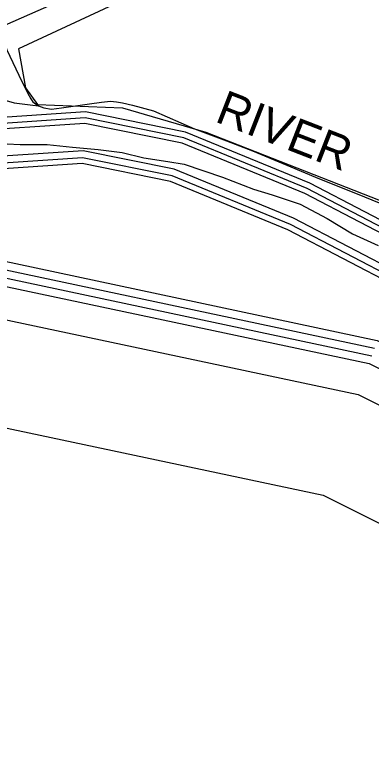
# Model space of a CAD drawing. Extents: x 2260773 to 2342389, y 552869 to 618546.
# Drawn here: x 2273724 to 2275474, y 592207 to 595865 of the extents above; entities that cross this region are included whole.
import ezdxf

# ---------------------------------------------------------------- set-up
doc = ezdxf.new("R2010")
doc.units = 0
for name, color, linetype in [('Exist Hydrographic Buffer Line', 7, 'Continuous'), ('Exist Hydrographic Lake Shore', 7, 'Continuous'), ('Exist Hydrographic Misc Water Feature', 7, 'Continuous'), ('Exist Hydrographic Pond Under 1500 Sq Ft', 7, 'Continuous'), ('Exist Hydrographic River Shore', 7, 'Continuous'), ('Exist Hydrographic River Shore Label', 7, 'Continuous'), ('Exist Road Non-System Type 51', 7, 'Continuous')]:
    doc.layers.add(name, color=color, linetype=linetype)

msp = doc.modelspace()

# ---------------------------------------------------------------- linework, layer by layer
at = {"layer": 'Exist Hydrographic Buffer Line'}
for points in [[(2280865.9, 594984.5), (2280052.8, 595165.8), (2279251.2, 595104.9), (2278777.9, 594983.9), (2278410.6, 594835.1), (2277854.3, 594325.9), (2277304, 594136.6), (2276736.5, 594234), (2276241.4, 594447.3), (2275159.9, 595011.2), (2274553.8, 595261.2), (2274069.4, 595358.9), (2273472.5, 595318.3), (2271849.6, 595062.1), (2271324.1, 595102.3)], [(2280857.6, 594958.9), (2280050.9, 595138.8), (2279255.6, 595078.4), (2278786.3, 594958.4), (2278425.1, 594812.1), (2277868.3, 594302.4), (2277306.3, 594109), (2276728.8, 594208.1), (2276229.9, 594423.1), (2275148.5, 594986.9), (2274545.9, 595235.4), (2274067.6, 595331.9), (2273475.5, 595291.6), (2271850.6, 595035.1), (2271322, 595075.6)], [(2280816.3, 594831.7), (2280041.2, 595004.5), (2279277.3, 594946.4), (2278828, 594831.5), (2278497.3, 594697.6), (2277937.8, 594185.5), (2277317.3, 593971.9), (2276690.7, 594079.5), (2276172.7, 594302.7), (2275092.3, 594866), (2274507, 595107.4), (2274058.8, 595197.8), (2273490.5, 595159.1), (2271856, 594901.1), (2271212.2, 594950.4)], [(2280805.8, 594799.1), (2280038.8, 594970.1), (2279282.9, 594912.6), (2278838.7, 594799.1), (2278515.8, 594668.3), (2277955.6, 594155.5), (2277320.2, 593936.8), (2276680.9, 594046.6), (2276158, 594271.9), (2275077.8, 594835), (2274497, 595074.6), (2274056.6, 595163.4), (2273494.3, 595125.2), (2271857.4, 594866.8), (2271248.4, 594913.4)], [(2275682.8, 590886.2), (2275298.9, 590908.5), (2274110.7, 590732.1), (2273660.6, 590686.4), (2273419.8, 590746.1), (2273239.6, 590939.8), (2273099.1, 591260.2), (2273064.9, 591446.4), (2272764.3, 591973.6), (2272546.3, 592252.6), (2272507.6, 592371.6), (2272512.7, 592725.7), (2272500.6, 592922.5), (2272230.5, 593239), (2272233.4, 593780.7), (2272721, 593822.7), (2272786.6, 593913.3), (2272785.8, 594399.9), (2273028.6, 594725.2), (2273146.3, 594725.5), (2275490.4, 594227.2)], [(2275694.1, 590924.5), (2275301.2, 590948.4), (2274105.5, 590771.8), (2273663.4, 590726.9), (2273441, 590782.1), (2273273.4, 590962), (2273137.7, 591271.9), (2273104.3, 591453.7), (2272798.9, 591993.5), (2272582.4, 592271.8), (2272547.7, 592377.7), (2272552.7, 592725.1), (2272540.4, 592925), (2272521.9, 592971.5), (2272270.9, 593254.1), (2272273.4, 593744), (2272724.3, 593782.9), (2272769, 593801.3), (2272822.5, 593895.9), (2272825.8, 594386.8), (2273048.9, 594685.3), (2273142.4, 594685.5), (2275477.1, 594189.2)], [(2272833.6, 592013.5), (2272618.1, 592290.8), (2272587.9, 592383.8), (2272592.6, 592724.6), (2272580.3, 592927.4), (2272564.6, 592980), (2272310.9, 593269.2), (2272313.2, 593707.3), (2272727.8, 593743), (2272777.6, 593758.7), (2272809.6, 593785.5), (2272858.6, 593878.5), (2272870.5, 593930.8), (2272866, 594373.7), (2273068.8, 594645.4), (2273138.1, 594645.5), (2275463.8, 594151.1), (2276254.1, 593757.8)], [(2272972.4, 592093.3), (2272761.6, 592367.2), (2272748.1, 592408.1), (2272752.6, 592722.4), (2272740.1, 592937.3), (2272723.7, 593015.8), (2272703.2, 593060), (2272675.1, 593100), (2272471.1, 593329.7), (2272472.3, 593560.4), (2272741.5, 593583.6), (2272813.3, 593599.5), (2272857.6, 593620.1), (2272897.6, 593648.1), (2272932, 593682.6), (2272960.1, 593722.6), (2273002.5, 593808.8), (2273026.3, 593882.1), (2273030.6, 593930.8), (2273026.5, 594321.3), (2273148.1, 594479.8), (2275410.7, 593998.8), (2276182.9, 593614.6)], [(2273719.2, 591838.2), (2273423.1, 592352.6), (2273359.5, 592446.6), (2273270.3, 592560.7), (2273272.6, 592715.2), (2273271.2, 592775.7), (2273259.1, 592969.5), (2273248.4, 593059), (2273212.3, 593193.6), (2273231.8, 593249.8), (2273330.4, 593348.3), (2273410.4, 593462.6), (2273437.7, 593514.1), (2273470.7, 593582.3), (2273502.3, 593657.2), (2273538.3, 593791.8), (2273544.9, 593863.8), (2275238, 593503.8), (2275951.4, 593149)]]:
    msp.add_lwpolyline(points, dxfattribs=at)
at = {"layer": 'Exist Hydrographic Lake Shore'}
msp.add_lwpolyline([(2272472.5, 592726.3), (2272460.6, 592920), (2272190.5, 593223.9), (2272193.6, 593817.5), (2272717.5, 593862.6), (2272750.5, 593930.8), (2272745.6, 594413), (2273008.5, 594765.2), (2273150.6, 594765.5), (2275503.6, 594265.3), (2276307.6, 593865.3), (2276724.7, 593742), (2277233.6, 593689.1), (2277591.6, 593708.1), (2277964.6, 593880.9), (2279148.6, 594591.5), (2279472.8, 594693.2), (2279788.7, 594722.9), (2280180.6, 594659.1), (2280557.7, 594530.2)], dxfattribs=at)
at = {"layer": 'Exist Hydrographic Misc Water Feature'}
msp.add_lwpolyline([(2273686.6, 595230.8), (2273750.8, 595227.6), (2273882.6, 595228.8), (2274006.7, 595215.8), (2274132.6, 595203.3), (2274251.3, 595188.3), (2274357.1, 595163.4), (2274475.6, 595144.3), (2274555.4, 595131.1), (2274743.6, 595067), (2274896.2, 595008.3), (2274988.7, 594981.4), (2275125, 594934.5), (2275257.7, 594863.8), (2275382.2, 594789.1), (2275508.7, 594732.3)], dxfattribs=at)
at = {"layer": 'Exist Hydrographic Pond Under 1500 Sq Ft'}
msp.add_lwpolyline([(2277070.6, 594204), (2277552.7, 594351.7), (2277593.7, 594377.1), (2277566.6, 594590.8), (2276469.6, 596931.7), (2276345.7, 596911.2), (2273741.6, 595698.1), (2273776.6, 595507.2), (2273835.7, 595424), (2274252.5, 595409), (2274661.6, 595289.2), (2275798.6, 594843.1), (2276636.7, 594301.3), (2276936.7, 594210), (2277070.6, 594204)], dxfattribs=at)
at = {"layer": 'Exist Hydrographic River Shore'}
for points in [[(2280875, 595012.6), (2280055, 595195.4), (2279246.4, 595134), (2278768.7, 595011.9), (2278394.6, 594860.4), (2277839, 594351.7), (2277301.6, 594166.8), (2276744.9, 594262.4), (2276254.1, 594473.9), (2275172.3, 595037.8), (2274562.3, 595289.4), (2274071.4, 595388.5), (2273469.2, 595347.5), (2271848.4, 595091.7), (2271326.3, 595131.6)], [(2280796.8, 594771.4), (2280036.7, 594940.8), (2279287.6, 594883.9), (2278847.8, 594771.5), (2278531.6, 594643.4), (2277970.8, 594130.1), (2277322.6, 593907), (2276672.6, 594018.6), (2276145.6, 594245.7), (2275065.6, 594808.7), (2274488.6, 595046.7), (2274054.7, 595134.2), (2273497.5, 595096.4), (2271858.6, 594837.6), (2271275.6, 594882.2)]]:
    msp.add_lwpolyline(points, dxfattribs=at)
at = {"layer": 'Exist Road Non-System Type 51'}
for points in [[(2277564.5, 594796.9), (2277510.4, 594924.8), (2277417.1, 595141.1), (2277242.6, 595529.5), (2277065.7, 595905.7), (2276903.5, 596267.1), (2276758.6, 596601.4), (2276621, 596891.5), (2276579.2, 596975.1), (2276544.8, 597016.9), (2276525.1, 597029.2), (2276488.3, 597043.9), (2276449, 597048.9), (2276419.5, 597046.4), (2276370.3, 597034.1), (2276247.5, 596984.9), (2275893.7, 596825.1), (2275414.5, 596603.9), (2274687.2, 596279.4), (2274237.6, 596070.4), (2273904.6, 595915.5), (2273645.4, 595802.4)], [(2273645.4, 595802.4), (2273684.7, 595694.3), (2273743.7, 595568.9), (2273785.5, 595482.8), (2273802.7, 595453.3), (2273812.5, 595438.6), (2273824.8, 595428.7), (2273839.5, 595418.9)], [(2273174.9, 595623), (2273238.8, 595591), (2273366.5, 595544.3), (2273518.9, 595497.6), (2273634.4, 595458.2), (2273720.4, 595433.7), (2273812.5, 595421.4), (2273839.5, 595418.9)], [(2273839.5, 595418.9), (2273866.6, 595409.1), (2273903.4, 595401.7), (2273952.6, 595409.1), (2274021.4, 595418.9), (2274090.1, 595428.7), (2274149.1, 595436.1), (2274193.3, 595441), (2274222.8, 595438.6), (2274252.3, 595433.7), (2274301.5, 595421.4), (2274404.7, 595394.3), (2274606.1, 595305.8), (2274763.4, 595246.8), (2274891.2, 595197.6), (2275060.7, 595126.3), (2275220.4, 595060), (2275404.7, 594986.2), (2275620.9, 594897.7)]]:
    msp.add_lwpolyline(points, dxfattribs=at)

# ---------------------------------------------------------------- texts
at = {"layer": 'Exist Hydrographic River Shore Label'}
msp.add_text('RIVER', height=167.32, rotation=338.7593, dxfattribs=at).set_placement((2274701.2, 595342.7))

doc.saveas('drawing.dxf')
